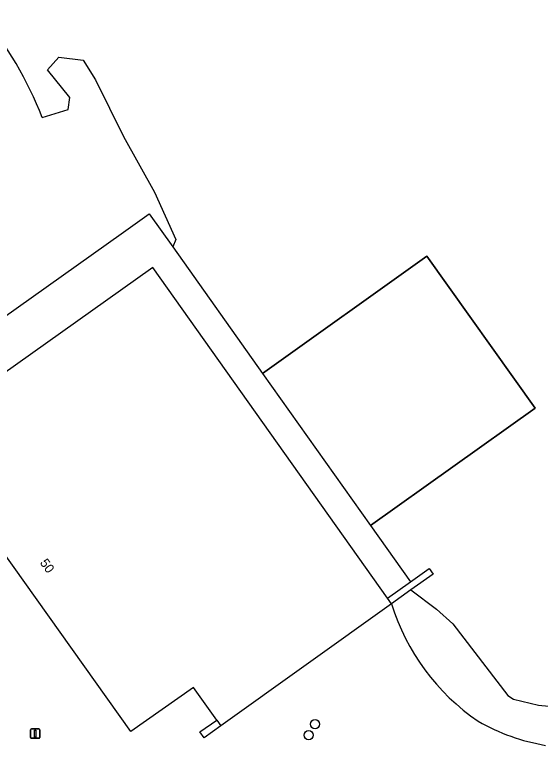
# Model space of a CAD drawing. Extents: x 163046 to 165074, y 382019 to 382874.
# Drawn here: x 164659.3 to 164715.7, y 382537 to 382615.4 of the extents above; entities that cross this region are included whole.
import ezdxf

# ---------------------------------------------------------------- set-up
doc = ezdxf.new("R2010")
doc.units = 0
for name, color, linetype in [('IMGEO_Afsluitpaal', 7, 'Continuous'), ('IMGEO_Boom', 7, 'Continuous'), ('IMGEO_Groenvoorziening', 7, 'Continuous'), ('IMGEO_Meer_plas_ven_vijver', 7, 'Continuous'), ('IMGEO_Muur', 7, 'Continuous'), ('IMGEO_Pand', 7, 'Continuous'), ('IMGEO_Pand_nummerreeks', 7, 'Continuous'), ('IMGEO_Steiger', 7, 'Continuous'), ('IMGEO_Waterloop', 7, 'Continuous')]:
    doc.layers.add(name, color=color, linetype=linetype)

msp = doc.modelspace()

# ---------------------------------------------------------------- linework, layer by layer
at = {"layer": 'IMGEO_Afsluitpaal'}
for p, q in [((164660.989, 382537.828), (164660.989, 382538.628)), ((164660.989, 382538.628), (164660.989, 382537.828)), ((164661.089, 382538.728), (164661.879, 382538.728)), ((164661.879, 382538.728), (164661.089, 382538.728)), ((164661.979, 382538.628), (164661.979, 382537.828)), ((164661.979, 382537.828), (164661.979, 382538.628)), ((164661.879, 382537.728), (164661.089, 382537.728)), ((164661.089, 382537.728), (164661.879, 382537.728))]:
    msp.add_line(p, q, dxfattribs=at)
msp.add_lwpolyline([(164661.409, 382538.603), (164661.559, 382538.603), (164661.559, 382537.853), (164661.409, 382537.853), (164661.409, 382538.603)], dxfattribs=at)
for centre, start, end in [((164661.089, 382538.628), 90, 180), ((164661.089, 382538.628), 90, 180), ((164661.879, 382538.628), 0, 90), ((164661.879, 382538.628), 360, 90), ((164661.089, 382537.828), 180, 270), ((164661.089, 382537.828), 180, 270), ((164661.879, 382537.828), 270, 0), ((164661.879, 382537.828), 270, 0)]:
    msp.add_arc(centre, 0.1, start, end, dxfattribs=at)
at = {"layer": 'IMGEO_Boom'}
for centre in [(164691.515, 382539.242), (164690.831, 382538.063)]:
    msp.add_circle(centre, 0.489, dxfattribs=at)
at = {"layer": 'IMGEO_Groenvoorziening'}
msp.add_lwpolyline([(164648.152, 382575.861), (164670.967, 382592.073), (164673.728, 382594.035), (164676.248, 382590.481)], dxfattribs=at)
for centre, radius, start, end in [((164722.611, 382559.325), 23.991, 197.38195, 235.48873), ((164720.041, 382558.945), 22.303, 240.38217, 260.2199)]:
    msp.add_arc(centre, radius, start, end, dxfattribs=at)
at = {"layer": 'IMGEO_Meer_plas_ven_vijver'}
msp.add_lwpolyline([(164685.887, 382576.883), (164697.462, 382560.556)], dxfattribs=at)
at = {"layer": 'IMGEO_Muur'}
for points in [[(164701.768, 382554.526), (164703.773, 382555.943), (164704.191, 382555.358), (164701.801, 382553.649)], [(164699.281, 382552.769), (164701.768, 382554.526)], [(164701.801, 382553.649), (164699.715, 382552.158)], [(164681.403, 382539.068), (164679.621, 382537.794), (164679.149, 382538.428), (164680.988, 382539.657)]]:
    msp.add_lwpolyline(points, dxfattribs=at)
at = {"layer": 'IMGEO_Pand'}
for points in [[(164699.281, 382552.769), (164674.103, 382588.253), (164649.682, 382570.927)], [(164680.988, 382539.657), (164678.495, 382543.191), (164671.763, 382538.445), (164648.982, 382570.43)], [(164699.715, 382552.158), (164699.281, 382552.769)], [(164699.715, 382552.158), (164681.403, 382539.068)], [(164680.988, 382539.657), (164681.403, 382539.068)]]:
    msp.add_lwpolyline(points, dxfattribs=at)
at = {"layer": 'IMGEO_Steiger'}
msp.add_lwpolyline([(164703.522, 382589.477), (164685.887, 382576.883), (164697.462, 382560.556), (164715.136, 382573.154)], close=True, dxfattribs=at)
at = {"layer": 'IMGEO_Waterloop'}
for points in [[(164662.25, 382604.356), (164665.042, 382605.229), (164665.223, 382606.529), (164662.804, 382609.499), (164664.02, 382610.831), (164666.651, 382610.519), (164667.979, 382608.416), (164670.979, 382602.321), (164674.285, 382596.348), (164676.579, 382591.261), (164676.248, 382590.481)], [(164676.248, 382590.481), (164685.887, 382576.883)], [(164685.887, 382576.883), (164703.522, 382589.477), (164715.136, 382573.154), (164697.462, 382560.556)], [(164697.462, 382560.556), (164701.768, 382554.526)], [(164701.801, 382553.649), (164704.542, 382551.591), (164706.312, 382550.019), (164712.186, 382542.306), (164712.801, 382541.938), (164715.492, 382541.295), (164716.6, 382541.172)]]:
    msp.add_lwpolyline(points, dxfattribs=at)
msp.add_arc((164625.279, 382590.013), 39.656, 21.20336, 39.83319, dxfattribs=at)

# ---------------------------------------------------------------- texts
at = {"layer": 'IMGEO_Pand_nummerreeks'}
msp.add_text('50', height=1, rotation=305.46063, dxfattribs=at).set_placement((164661.953, 382556.562))

doc.saveas('drawing.dxf')
